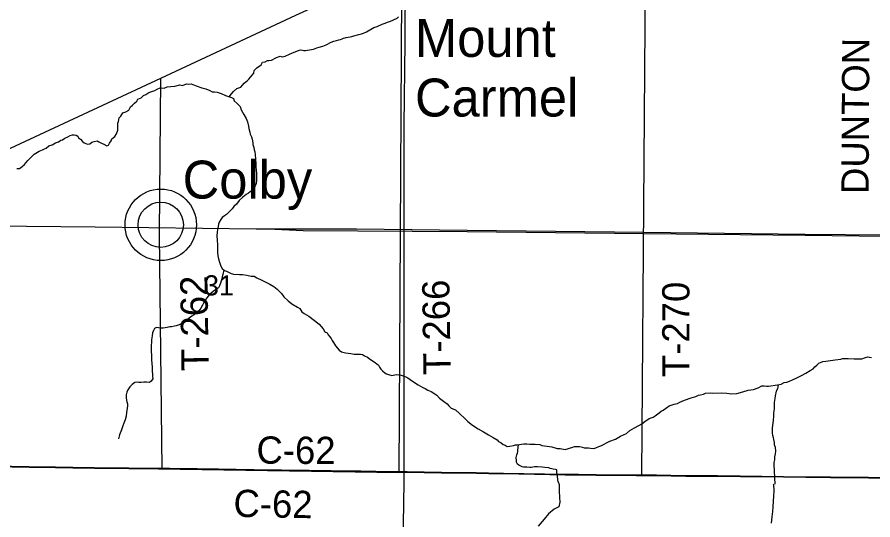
# Model space of a CAD drawing. Extents: x -8.5 to 18.7, y -20.3 to 7.
# Drawn here: x 11.845 to 15.411, y -11.043 to -8.949 of the extents above; entities that cross this region are included whole.
import ezdxf

# ---------------------------------------------------------------- set-up
doc = ezdxf.new("R2010")
doc.units = 0
for name, color, linetype in [('GM_X_Corporation', 7, 'Continuous'), ('GM_X_County_Road', 7, 'Continuous'), ('GM_X_County_Road_Text', 7, 'Continuous'), ('GM_X_Minor_River', 7, 'Continuous'), ('GM_X_Rail_Line', 7, 'Continuous'), ('GM_X_Section', 7, 'Continuous'), ('GM_X_Section_Text', 7, 'Continuous'), ('GM_X_Township_Road', 7, 'Continuous'), ('GM_X_Township_Road_Text', 7, 'Continuous'), ('GM_X_Unincorporated', 7, 'Continuous'), ('GM_X_Unincorporated_Location', 7, 'Continuous'), ('GM_X_Unincorporated_Text', 7, 'Continuous'), ('SH_Cut_Line', 7, 'Continuous')]:
    doc.layers.add(name, color=color, linetype=linetype)

msp = doc.modelspace()

# ---------------------------------------------------------------- linework, layer by layer
at = {"layer": 'GM_X_Corporation'}
for points in [[(15.4437, -10.867), (15.3932, -10.8666), (15.2341, -10.8654), (15.1321, -10.8643), (15.0389, -10.8629), (14.8586, -10.8612), (14.7641, -10.86), (14.6311, -10.8591), (14.5093, -10.8572), (14.4484, -10.8569), (14.4261, -10.8568), (14.3416, -10.8559), (14.2584, -10.8552), (14.1851, -10.8543), (14.1279, -10.8539), (13.8718, -10.849), (13.8097, -10.8482), (13.7587, -10.8475), (13.6829, -10.8464), (13.6133, -10.8454), (13.5412, -10.8446), (13.4704, -10.8429), (13.4574, -10.8428), (13.4503, -10.8427), (13.402, -10.8423), (13.2777, -10.8405), (13.1981, -10.8395), (13.1534, -10.839), (13.0626, -10.8372), (13.0266, -10.8366), (12.947, -10.8363), (12.8314, -10.8342), (12.6848, -10.8314), (12.5952, -10.8304), (12.4821, -10.8289), (12.4496, -10.8286), (12.3106, -10.8275), (12.1663, -10.8257), (12.0768, -10.8243), (12.0047, -10.8233), (11.8941, -10.8215), (11.7474, -10.8194)], [(11.7474, -10.8194), (11.8941, -10.8215), (12.0047, -10.8233), (12.0768, -10.8243), (12.1663, -10.8257), (12.3106, -10.8275), (12.4496, -10.8286), (12.4821, -10.8289), (12.5952, -10.8304), (12.6848, -10.8314), (12.8314, -10.8342), (12.947, -10.8363), (13.0266, -10.8366), (13.0626, -10.8372), (13.1534, -10.839), (13.1981, -10.8395), (13.2777, -10.8405), (13.402, -10.8423), (13.4503, -10.8427), (13.4574, -10.8428), (13.4704, -10.8429), (13.5412, -10.8446), (13.6133, -10.8454), (13.6829, -10.8464), (13.7587, -10.8475), (13.8097, -10.8482), (13.8718, -10.849), (14.1279, -10.8539), (14.1851, -10.8543), (14.2584, -10.8552), (14.3416, -10.8559), (14.4261, -10.8568), (14.4484, -10.8569), (14.5093, -10.8572), (14.6311, -10.8591), (14.7641, -10.86), (14.8586, -10.8612), (15.0389, -10.8629), (15.1321, -10.8643), (15.2341, -10.8654), (15.3932, -10.8666), (15.4437, -10.867)]]:
    msp.add_lwpolyline(points, dxfattribs=at)
at = {"layer": 'GM_X_County_Road'}
for points in [[(11.4546, -9.6627), (12.4441, -9.2033), (13.0064, -8.9417), (13.1807, -8.8606), (13.4526, -8.7299), (13.5606, -8.6794), (13.7291, -8.5973), (14.1473, -8.386), (14.4736, -8.218)], [(11.4376, -10.8165), (11.442, -10.8165), (11.7093, -10.8199), (11.7478, -10.8205), (11.8945, -10.8226), (12.0051, -10.8244), (12.0773, -10.8254), (12.1668, -10.8268), (12.311, -10.8286), (12.4501, -10.8297)], [(12.4501, -10.8297), (12.4826, -10.83), (12.5957, -10.8315), (12.6852, -10.8325), (12.8319, -10.8353), (12.9475, -10.8374), (13.0271, -10.8377), (13.0631, -10.8383), (13.1538, -10.8401), (13.1986, -10.8406), (13.2781, -10.8416), (13.4024, -10.8434), (13.4508, -10.8438), (13.4579, -10.8439)], [(13.4579, -10.8439), (13.4708, -10.844), (13.5416, -10.8457), (13.6138, -10.8465), (13.6834, -10.8475), (13.7592, -10.8486), (13.8102, -10.8493), (13.8723, -10.8501), (14.1284, -10.855), (14.1855, -10.8554), (14.2588, -10.8563), (14.342, -10.857), (14.4265, -10.8579), (14.4489, -10.858)], [(14.4489, -10.858), (14.5097, -10.8583), (14.6315, -10.8602), (14.7646, -10.8611), (14.859, -10.8623), (15.0393, -10.864), (15.1325, -10.8654), (15.2345, -10.8665), (15.3936, -10.8677), (15.4442, -10.8681)]]:
    msp.add_lwpolyline(points, dxfattribs=at)
at = {"layer": 'GM_X_Minor_River'}
for points in [[(12.7273, -9.28), (12.7309, -9.2764), (12.7463, -9.2591), (12.76, -9.2471), (12.7767, -9.2404), (12.7913, -9.2245), (12.805, -9.2133), (12.8111, -9.208), (12.8249, -9.1907), (12.8318, -9.1824), (12.8327, -9.1718), (12.8434, -9.1605), (12.8617, -9.1485), (12.8679, -9.1371), (12.8785, -9.135), (12.8884, -9.1305), (12.8945, -9.1305), (12.9051, -9.1291), (12.9264, -9.1179), (12.9409, -9.1112), (12.9492, -9.1143), (12.956, -9.1136), (12.9614, -9.1121), (12.9804, -9.1032), (13.0002, -9.095), (13.0177, -9.0876), (13.0245, -9.0861), (13.0336, -9.087), (13.0397, -9.0878), (13.0473, -9.0878), (13.0556, -9.0872), (13.0799, -9.0828), (13.0944, -9.0769), (13.1035, -9.0747), (13.1187, -9.0702), (13.1324, -9.0651), (13.1537, -9.0531), (13.1652, -9.0494), (13.1758, -9.0464), (13.1857, -9.0443), (13.1925, -9.0428), (13.1994, -9.0398), (13.2055, -9.0376), (13.2115, -9.0354), (13.2169, -9.0339), (13.2245, -9.0325), (13.2336, -9.0318), (13.2404, -9.0296), (13.2488, -9.0274), (13.2685, -9.0222), (13.2799, -9.0185), (13.2883, -9.0156), (13.3005, -9.0111), (13.3317, -8.9924), (13.3454, -8.988), (13.366, -8.979), (13.3751, -8.9761), (13.3926, -8.9686), (13.3987, -8.9679), (13.4139, -8.9605), (13.4284, -8.953), (13.4337, -8.9477)], [(12.0906, -9.4415), (12.0982, -9.4445), (12.1006, -9.4521), (12.1097, -9.4581), (12.1173, -9.4672), (12.125, -9.4732), (12.1379, -9.4777), (12.1477, -9.4769), (12.1568, -9.47), (12.1659, -9.4677), (12.178, -9.4638), (12.1857, -9.4684), (12.1963, -9.4744), (12.2062, -9.4781), (12.2184, -9.4857), (12.226, -9.4818), (12.2297, -9.4742), (12.2373, -9.4643), (12.2395, -9.4567), (12.2524, -9.446), (12.2591, -9.4346), (12.2651, -9.4201), (12.265, -9.3912), (12.2672, -9.3836), (12.2702, -9.3692), (12.277, -9.3616), (12.286, -9.3478), (12.2974, -9.344), (12.311, -9.3363), (12.3178, -9.3226), (12.3253, -9.3157), (12.3344, -9.3073), (12.3442, -9.2989), (12.3487, -9.2913), (12.3616, -9.2852), (12.3714, -9.276), (12.3813, -9.2714), (12.3934, -9.2638), (12.4017, -9.2599), (12.4184, -9.2545), (12.4283, -9.2492), (12.4411, -9.2438), (12.4571, -9.2452), (12.4707, -9.2398), (12.4851, -9.2375), (12.5018, -9.2366), (12.5231, -9.2312), (12.5345, -9.2342), (12.5511, -9.2273), (12.5595, -9.228), (12.5701, -9.2272), (12.5906, -9.2355), (12.6142, -9.2437), (12.6317, -9.2482), (12.6477, -9.2549), (12.6576, -9.2602), (12.6674, -9.2609), (12.6781, -9.2616), (12.6872, -9.2646), (12.6948, -9.2669), (12.7138, -9.2751), (12.726, -9.2796), (12.7389, -9.2834), (12.7465, -9.2879), (12.7496, -9.2978), (12.7626, -9.3091), (12.7748, -9.3212), (12.7787, -9.3356), (12.7901, -9.3553), (12.7993, -9.372), (12.8047, -9.3849), (12.8094, -9.4038), (12.8109, -9.4129), (12.8148, -9.4281), (12.8164, -9.4365), (12.8217, -9.4471), (12.8248, -9.4569), (12.8272, -9.4721), (12.828, -9.4797), (12.8311, -9.4926), (12.8334, -9.5017), (12.835, -9.5101), (12.8365, -9.5215), (12.8381, -9.5405), (12.8398, -9.5602), (12.8398, -9.5708), (12.8407, -9.5883), (12.8422, -9.5974), (12.843, -9.6073), (12.8431, -9.6156), (12.8424, -9.6232), (12.8424, -9.6316), (12.8409, -9.6415), (12.8372, -9.6521), (12.8289, -9.6651), (12.8168, -9.6766), (12.8093, -9.6827), (12.7994, -9.688), (12.785, -9.6987), (12.7707, -9.7132), (12.7586, -9.7277)], [(11.8431, -9.5802), (11.8545, -9.5793), (11.8658, -9.5717), (11.8756, -9.5633), (11.8892, -9.5458), (11.9089, -9.5267), (11.9164, -9.5198), (11.9368, -9.5075), (11.9505, -9.5014), (11.9588, -9.4976), (11.9664, -9.4945), (11.9777, -9.4853), (11.9906, -9.4807), (12.005, -9.4723), (12.0171, -9.4684), (12.027, -9.4615), (12.0345, -9.46), (12.0436, -9.4538), (12.0557, -9.4477), (12.0663, -9.4416), (12.0754, -9.4393), (12.083, -9.4392), (12.0906, -9.4415)], [(12.7586, -9.7277), (12.748, -9.7377), (12.7405, -9.7476), (12.7178, -9.7705), (12.7088, -9.7766), (12.6997, -9.7842), (12.6937, -9.7926), (12.6876, -9.8025), (12.6839, -9.8117), (12.6824, -9.8208), (12.6794, -9.8337), (12.678, -9.8444), (12.6773, -9.8603), (12.6781, -9.8778), (12.6798, -9.8968), (12.6806, -9.9044), (12.6807, -9.9279), (12.6815, -9.9439), (12.6839, -9.9553), (12.6869, -9.9659), (12.69, -9.9742), (12.6939, -9.9864), (12.6992, -9.9954), (12.7099, -10.0038), (12.7175, -10.0068), (12.7373, -10.0165), (12.7517, -10.021), (12.7616, -10.0202), (12.7722, -10.0217), (12.7836, -10.0209), (12.8026, -10.0238), (12.8209, -10.0275), (12.8323, -10.0282), (12.8444, -10.035), (12.8642, -10.044), (12.884, -10.0538), (12.8985, -10.0606), (12.9145, -10.0704), (12.9289, -10.0825), (12.9381, -10.0916), (12.9465, -10.1006), (12.9564, -10.1135), (12.974, -10.1309), (12.99, -10.143), (13.0136, -10.1565), (13.0227, -10.1626), (13.0319, -10.177), (13.0411, -10.183), (13.0601, -10.1943), (13.0837, -10.2124), (13.1043, -10.2283), (13.1211, -10.2472), (13.1272, -10.2593), (13.1364, -10.2646), (13.141, -10.2729), (13.1486, -10.2805), (13.1532, -10.2881), (13.1585, -10.2964), (13.1639, -10.304), (13.1715, -10.3176), (13.1876, -10.3358), (13.1967, -10.3433), (13.2134, -10.347), (13.2362, -10.35), (13.2499, -10.3529), (13.2666, -10.3521), (13.2757, -10.3528), (13.2841, -10.3543), (13.2925, -10.3596), (13.3054, -10.3656), (13.3176, -10.3746), (13.3374, -10.3875), (13.3504, -10.398), (13.3557, -10.4071), (13.3611, -10.4147), (13.3672, -10.4223), (13.3771, -10.4306), (13.3847, -10.4343), (13.3923, -10.4373), (13.4067, -10.4411), (13.425, -10.4372), (13.4363, -10.4394), (13.4455, -10.4401), (13.4576, -10.4446), (13.4652, -10.4469), (13.4736, -10.4514), (13.4934, -10.465), (13.517, -10.4801), (13.5361, -10.4914), (13.5452, -10.4959), (13.5566, -10.5027), (13.5703, -10.5079), (13.5855, -10.5185), (13.5947, -10.5237), (13.6054, -10.5359), (13.6214, -10.5487), (13.6374, -10.5593), (13.6435, -10.5676), (13.6542, -10.5782), (13.6717, -10.5842), (13.6884, -10.5993)], [(12.7066, -10.0012), (12.7016, -10.0205), (12.7002, -10.0312), (12.6972, -10.0433), (12.6942, -10.0532), (12.689, -10.0684), (12.6845, -10.0761), (12.6678, -10.0875), (12.6557, -10.0975), (12.6459, -10.1059), (12.6278, -10.1287), (12.6233, -10.1379), (12.618, -10.1493), (12.6112, -10.1607), (12.6022, -10.1722), (12.5931, -10.1813), (12.5825, -10.189), (12.5727, -10.1951), (12.5621, -10.2028), (12.553, -10.2096), (12.5417, -10.2196), (12.5334, -10.2242), (12.5243, -10.2288), (12.5084, -10.2349), (12.5008, -10.2365), (12.4887, -10.2388), (12.4811, -10.2396), (12.4697, -10.2412), (12.4621, -10.2427), (12.4538, -10.2451), (12.4447, -10.2451), (12.4348, -10.2429), (12.4257, -10.2422), (12.4173, -10.246), (12.4128, -10.2544), (12.4098, -10.2635), (12.4076, -10.2764), (12.4061, -10.2848), (12.4054, -10.2932), (12.4047, -10.303), (12.404, -10.3167), (12.4042, -10.3433), (12.405, -10.3562), (12.405, -10.3653), (12.4051, -10.3767), (12.4075, -10.4064), (12.4083, -10.417), (12.4084, -10.4253), (12.4092, -10.4345), (12.4092, -10.4459), (12.41, -10.455), (12.404, -10.4649), (12.3964, -10.4702), (12.3843, -10.4695), (12.3737, -10.4688), (12.3623, -10.4704), (12.3524, -10.4704), (12.3448, -10.4697), (12.3357, -10.4705), (12.3251, -10.4789), (12.3145, -10.4889), (12.3063, -10.501), (12.3025, -10.5109), (12.2995, -10.5224), (12.2988, -10.5345), (12.3012, -10.5436), (12.3027, -10.5512), (12.3043, -10.5596), (12.3043, -10.5679), (12.3036, -10.5778), (12.3007, -10.5953), (12.2992, -10.6105), (12.2955, -10.6265), (12.2903, -10.6402), (12.2858, -10.6516), (12.2828, -10.6599), (12.2798, -10.6676), (12.2745, -10.6813), (12.2715, -10.6889), (12.2671, -10.7056)], [(15.2148, -10.3816), (15.2247, -10.38), (15.2535, -10.3761), (15.2778, -10.3729), (15.2853, -10.3713), (15.3089, -10.3705), (15.3339, -10.3719), (15.3491, -10.3726), (15.3658, -10.3717), (15.381, -10.3671), (15.3901, -10.364), (15.3977, -10.3647), (15.406, -10.3662)], [(13.6884, -10.5993), (13.7121, -10.6227), (13.7235, -10.6325), (13.7433, -10.6484), (13.7662, -10.6635), (13.789, -10.6763), (13.8096, -10.6891), (13.8294, -10.6997), (13.8454, -10.7094), (13.8515, -10.717), (13.8621, -10.7223), (13.8705, -10.7283), (13.8789, -10.7313), (13.8873, -10.7366), (13.8987, -10.7365), (13.9131, -10.7327), (13.9214, -10.7304), (13.929, -10.7303), (13.9563, -10.7256), (13.9692, -10.7263), (13.9821, -10.7278), (13.995, -10.727), (14.0041, -10.7269), (14.0239, -10.7291), (14.0315, -10.7329), (14.0535, -10.7358), (14.0733, -10.738), (14.0961, -10.7462), (14.1082, -10.7462), (14.1288, -10.7499), (14.1606, -10.7406), (14.1682, -10.7368), (14.1887, -10.7374), (14.2008, -10.7404), (14.2084, -10.7427), (14.2175, -10.7434), (14.2267, -10.7433), (14.235, -10.7448), (14.2487, -10.7455), (14.257, -10.7424), (14.2691, -10.7371), (14.2775, -10.7347), (14.3153, -10.7156), (14.3381, -10.7071), (14.36, -10.6948), (14.3843, -10.6826), (14.3986, -10.6711), (14.4183, -10.6589), (14.4357, -10.6504), (14.4478, -10.6435), (14.4614, -10.6336), (14.4796, -10.6213), (14.4955, -10.6144), (14.5038, -10.6091), (14.5205, -10.5968), (14.5296, -10.5899), (14.5379, -10.5861), (14.547, -10.5785), (14.5628, -10.5685), (14.575, -10.5639), (14.5825, -10.5608), (14.597, -10.5577), (14.6068, -10.5531), (14.6257, -10.5447), (14.6545, -10.5346), (14.6735, -10.5285), (14.6841, -10.5239), (14.6924, -10.5223), (14.7053, -10.5192), (14.7137, -10.5146), (14.7349, -10.5137), (14.7433, -10.5145), (14.7789, -10.5143), (14.8032, -10.5157), (14.8222, -10.5179), (14.845, -10.5163), (14.87, -10.5101), (14.8912, -10.5031), (14.914, -10.4992), (14.9337, -10.4931), (14.9488, -10.4846), (14.958, -10.4846), (14.9678, -10.4853), (14.9769, -10.486), (15.0141, -10.4805), (15.0285, -10.4782), (15.0422, -10.4713), (15.0528, -10.4697), (15.0634, -10.4651), (15.077, -10.4597), (15.0914, -10.4528), (15.1141, -10.4421), (15.1323, -10.4313), (15.1505, -10.4214), (15.1618, -10.4137), (15.1701, -10.4061), (15.1784, -10.3992), (15.186, -10.3908), (15.1936, -10.387), (15.2034, -10.3831), (15.2148, -10.3816)], [(15.016, -10.4802), (15.0157, -10.4889), (15.0134, -10.4965), (15.0089, -10.5071), (15.0045, -10.5261), (15.0022, -10.5368), (15.0015, -10.5459), (14.9993, -10.5543), (14.9994, -10.5794), (14.9987, -10.5907), (14.9972, -10.5984), (14.9965, -10.6113), (14.9951, -10.628), (14.9937, -10.6402), (14.9922, -10.6592), (14.9915, -10.6675), (14.9916, -10.6812), (14.9931, -10.6903), (14.9962, -10.7002), (14.9978, -10.7085), (15.0001, -10.7207), (15.0002, -10.7283), (15.004, -10.7404), (15.0049, -10.7563), (15.0042, -10.7677), (15.002, -10.7807), (15.0013, -10.7928), (14.999, -10.8035), (14.9983, -10.8118), (15.0022, -10.8936)], [(14.1003, -10.8841), (14.0951, -10.852), (14.0944, -10.8459), (14.0945, -10.8406), (14.0937, -10.8345), (14.0885, -10.8329), (14.0794, -10.8313), (14.0733, -10.8298), (14.0665, -10.8289), (14.0612, -10.8266), (14.0445, -10.825), (14.0332, -10.8226), (14.0135, -10.8224), (14.0006, -10.8223), (13.9876, -10.8245), (13.9823, -10.8244), (13.9687, -10.8235), (13.9619, -10.8235), (13.9551, -10.8226), (13.9497, -10.8218), (13.9437, -10.8195), (13.9361, -10.8156), (13.9301, -10.8103), (13.9264, -10.8027), (13.9257, -10.7958), (13.9243, -10.7836), (13.9259, -10.7768), (13.9274, -10.7715), (13.9297, -10.7655), (13.9313, -10.7587), (13.9321, -10.7533), (13.9342, -10.7291)], [(14.1, -10.8845), (14.1038, -10.8948), (14.1038, -10.9221), (14.106, -10.9494), (14.1067, -10.9684), (14.1028, -10.9889), (14.0831, -10.998), (14.0588, -11.0177), (14.0413, -11.0397), (14.017, -11.0685)], [(14.9951, -10.8935), (14.9967, -10.8951), (14.9981, -10.9224), (14.9966, -10.9444), (14.9958, -10.9649), (14.9942, -10.9885), (14.9926, -11.0082), (14.9896, -11.0302), (14.988, -11.0568)]]:
    msp.add_lwpolyline(points, dxfattribs=at)
at = {"layer": 'GM_X_Rail_Line'}
for points in [[(11.4534, -9.8155), (12.1707, -9.8232), (12.8412, -9.8307), (12.89, -9.8312)], [(12.89, -9.8312), (13.0368, -9.838), (13.7204, -9.8413), (14.4568, -9.8502), (15.1286, -9.8576), (15.4663, -9.8613), (16.0952, -9.8687), (16.7625, -9.8757), (17.4838, -9.8838), (18.4771, -9.8949), (18.7413, -9.8978)], [(12.89, -9.8312), (13.26, -9.8312), (13.7204, -9.8364), (14.4569, -9.8452), (15.1286, -9.8526), (15.4664, -9.8563), (16.0953, -9.8637), (16.7626, -9.8707), (17.4839, -9.8789), (18.4771, -9.89), (18.7413, -9.8928)]]:
    msp.add_lwpolyline(points, dxfattribs=at)
at = {"layer": 'GM_X_Section'}
msp.add_lwpolyline([(11.4531, -8.8156), (13.4473, -8.8495), (13.4352, -10.8471), (11.4305, -10.8167)], close=True, dxfattribs=at)
at = {"layer": 'GM_X_Township_Road'}
msp.add_line((12.4381, -9.8505), (12.4441, -9.2033), dxfattribs=at)
for points in [[(14.4489, -10.858), (14.4674, -8.2358), (14.4736, -8.218)], [(13.4579, -10.8439), (13.4585, -9.4012), (13.462, -9.0532), (13.4642, -8.7866), (13.4636, -8.7506), (13.4597, -8.7407), (13.4526, -8.7299)], [(12.4501, -10.8297), (12.4381, -9.8564), (12.4381, -9.8505)], [(13.4246, -12.8443), (13.4248, -12.8298), (13.4258, -12.7415), (13.4291, -12.463), (13.4307, -12.3723), (13.4319, -12.2454), (13.4348, -12.059), (13.4362, -11.9384), (13.4384, -11.8787), (13.4406, -11.8066), (13.4414, -11.7606), (13.4433, -11.6886), (13.444, -11.6289), (13.4442, -11.6153), (13.4456, -11.5656), (13.448, -11.4413), (13.4503, -11.3058), (13.4521, -11.2188), (13.4547, -11.0609), (13.4578, -10.8856), (13.4578, -10.8558), (13.4579, -10.8439)]]:
    msp.add_lwpolyline(points, dxfattribs=at)
at = {"layer": 'GM_X_Unincorporated'}
for radius in [0.1488, 0.0943]:
    msp.add_circle((12.4435, -9.814), radius, dxfattribs=at)
at = {"layer": 'GM_X_Unincorporated_Location'}
msp.add_line((12.4435, -9.814), (12.4435, -9.814), dxfattribs=at)
at = {"layer": 'SH_Cut_Line'}
for points in [[(15.4437, -10.867), (15.3932, -10.8666), (15.2341, -10.8654), (15.1321, -10.8643), (15.0389, -10.8629), (14.8586, -10.8612), (14.7641, -10.86), (14.6311, -10.8591), (14.5093, -10.8572), (14.4484, -10.8569), (14.4261, -10.8568), (14.3416, -10.8559), (14.2584, -10.8552), (14.1851, -10.8543), (14.1279, -10.8539), (13.8718, -10.849), (13.8097, -10.8482), (13.7587, -10.8475), (13.6829, -10.8464), (13.6133, -10.8454), (13.5412, -10.8446), (13.4704, -10.8429), (13.4574, -10.8428), (13.4503, -10.8427), (13.402, -10.8423), (13.2777, -10.8405), (13.1981, -10.8395), (13.1534, -10.839), (13.0626, -10.8372), (13.0266, -10.8366), (12.947, -10.8363), (12.8314, -10.8342), (12.6848, -10.8314), (12.5952, -10.8304), (12.4821, -10.8289), (12.4496, -10.8286), (12.3106, -10.8275), (12.1663, -10.8257), (12.0768, -10.8243), (12.0047, -10.8233), (11.8941, -10.8215), (11.7474, -10.8194)], [(11.7474, -10.8194), (11.8941, -10.8215), (12.0047, -10.8233), (12.0768, -10.8243), (12.1663, -10.8257), (12.3106, -10.8275), (12.4496, -10.8286), (12.4821, -10.8289), (12.5952, -10.8304), (12.6848, -10.8314), (12.8314, -10.8342), (12.947, -10.8363), (13.0266, -10.8366), (13.0626, -10.8372), (13.1534, -10.839), (13.1981, -10.8395), (13.2777, -10.8405), (13.402, -10.8423), (13.4503, -10.8427), (13.4574, -10.8428), (13.4704, -10.8429), (13.5412, -10.8446), (13.6133, -10.8454), (13.6829, -10.8464), (13.7587, -10.8475), (13.8097, -10.8482), (13.8718, -10.849), (14.1279, -10.8539), (14.1851, -10.8543), (14.2584, -10.8552), (14.3416, -10.8559), (14.4261, -10.8568), (14.4484, -10.8569), (14.5093, -10.8572), (14.6311, -10.8591), (14.7641, -10.86), (14.8586, -10.8612), (15.0389, -10.8629), (15.1321, -10.8643), (15.2341, -10.8654), (15.3932, -10.8666), (15.4437, -10.867)]]:
    msp.add_lwpolyline(points, dxfattribs=at)

# ---------------------------------------------------------------- texts
at = {"layer": 'GM_X_County_Road_Text'}
for rotation, p in [(359.6636, (12.8423, -10.8086)), (358.9692, (12.7459, -11.0301))]:
    msp.add_text('C-62', height=0.11364, rotation=rotation, dxfattribs=at).set_placement(p)
at = {"layer": 'GM_X_Section_Text'}
msp.add_text('31', height=0.08371, rotation=0, dxfattribs=at).set_placement((12.624, -10.108))
at = {"layer": 'GM_X_Township_Road_Text'}
for s, rotation, p in [('DUNTON', 89.6746, (15.3934, -9.6862)), ('T-262', 90.8421, (12.6437, -10.4219)), ('T-266', 90.8421, (13.652, -10.4386)), ('T-270', 90, (14.647, -10.4481))]:
    msp.add_text(s, height=0.11364, rotation=rotation, dxfattribs=at).set_placement(p)
at = {"layer": 'GM_X_Unincorporated_Text'}
for s, p in [('Mount', (13.5031, -9.1149)), ('Carmel', (13.5031, -9.3632)), ('Colby', (12.5348, -9.7049))]:
    msp.add_text(s, height=0.15795, rotation=0, dxfattribs=at).set_placement(p)

doc.saveas('drawing.dxf')
